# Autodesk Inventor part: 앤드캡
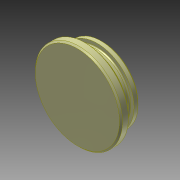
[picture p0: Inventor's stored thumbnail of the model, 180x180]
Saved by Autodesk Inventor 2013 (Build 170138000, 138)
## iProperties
Created: 2023-03
Part Number: 앤드캡
Material: 알루미늄 6061
Document SubType Name: Modeling
Designer: mdu-01
Density: 1 g/cm^3
Author: mdu-01
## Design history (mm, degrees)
sketch "스케치1"
  geometry: L1 (0, 0)-(0, 17); L2 (0, 17)-(24, 17); L3 (25, 6)-(28.5, 6); L4 (29.5, 5)-(29.5, 1); L5 (28.5, 0)-(0, 0); L6 (29.5, 1)-(28.5, 0); L7 (24, 17)-(25, 16); L8 (25, 13.35)-(22.8, 13.35); L9 (22, 12.55)-(22, 9.45); L10 (22.8, 8.65)-(25, 8.65); L11 (22, 11)-(25, 11); L12 (25, 16)-(25, 13.35); L13 (25, 8.65)-(25, 6); L14 (25, 9)-(25, 62) reference; L15 (28.5, 6)-(29.5, 5); A1 r 0.8 centre (22.8, 9.45) between (22, 9.45) and (22.8, 8.65); A2 r 0.8 centre (22.8, 12.55) between (22.8, 13.35) and (22, 12.55); 3 further points
  constraints: 31 end point, 8 perpendicular, 6 point on line, 4 parallel, 4 point on circle, 4 tangent, 2 centre point, 2 collinear, 2 vertical, 1 equal radius, 1 midpoint, 2 other
  dimensions: "d0" = 17 distance of L1.end L1.start; "d1" = 11 distance between parallel lines of L3 L2; "d6" = 1 distance of L4.end point (29.5, 0); "d7" = 1 distance of L5.start point (29.5, 0) (= d6); "d8" = 1 distance of L2.end point (25, 17) (= d6); "d9" = 1 distance of L7.end point (25, 17) (= d8); "d11" = 6 distance between parallel lines of L11 L2; "d12" = 4.7 distance between parallel lines of L10 L8; "d13" = 44 diameter of L9 L1; "d15" = 0.8 radius of A2; "d37" = 1 distance of L3.end point (29.5, 6); "d38" = 1 distance of L4.start point (29.5, 6) (= d37); "d39" = 59 diameter of L4 L1
revolve "회전1" sketch "스케치1" stored, may be unused: angle "d16" = 90 deg
node "솔리드1"
